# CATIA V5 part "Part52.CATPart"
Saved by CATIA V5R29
Part number: spur gear_iso_ISO - Spur gear 0.5M 13T 20PA 7FW ---S13A75H50L3.0N
Revision: ANY
Definition: UNKNOWN
Nomenclature: spur gear_iso_ISO - Spur gear 0.5M 13T 20PA 7FW ---S13A75H50L3.0N
Source: Unknown
Bounding box of the stored display mesh (mm): x 0 to 7, y -3.749 to 3.663, z -3.733 to 3.733
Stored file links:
  C:\Users\Administrator\Desktop\프로젝트\Gripper\Part52.CATPart
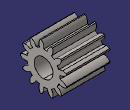
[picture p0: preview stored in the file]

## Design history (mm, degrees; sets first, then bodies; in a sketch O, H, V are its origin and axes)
Body1 "Bore" (main body)
  Solid1: solid without history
